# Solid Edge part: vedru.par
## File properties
Author: KULL
Template: Iso Metric Part.par
Last saved by: KULL
Revision: 3
Application: Solid Edge
Accuracy: 0,990
Face Style: Model Default
Fill Style: Normal
Coef. of Thermal Exp: 0.0
Thermal Conductivity: 0.0
Specific Heat: 0.0
Modulus of Elasticity: 0.0
Poisson's Ratio: 0.0
Yield Stress: 0.0
Ultimate Stress: 0.0
Elongation: 0.0
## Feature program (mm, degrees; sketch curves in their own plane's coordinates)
helix protrusion "HelixProtrusion_1"  NumberOfTurns = 4.5
sketch for "unnamed RevolvedProtrusion 1" plane through (0, 0, 0) normal (1, 0, 0) x-axis (0, 1, 0)
  circle centre (54.7904, 36.9537) radius 1.2
revolve "unnamed RevolvedProtrusion 1" add finite 360 deg
sketch for "unnamed RevolvedProtrusion 2" plane through (0, 0, 0) normal (1, 0, 0) x-axis (0, 1, 0)
  circle centre (78.3263, 18.3837) radius 1.2
revolve "unnamed RevolvedProtrusion 2" add finite 360 deg
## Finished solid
Body 1: solid body, 3 faces, 4 edges, 4 vertices.
  Faces by surface: torus 2, spline 1
  Edges by curve: circle 2, intersection 2
Bounding box of the edges (mm; curved faces can reach further): 6.787 x 25.640 x 26.544, from (-6.7872, 53.7383, 14.3974) to (0, 79.3784, 40.9412).
Toroidal faces (ring radius, tube radius in mm): R5.8516 r1.2 x2
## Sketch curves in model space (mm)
line (0, 73.196, 15.5693) -> (0, 59.9207, 39.7682)
circle centre (0, 54.7904, 36.9537) radius 1.2
circle centre (0, 78.3263, 18.3837) radius 1.2
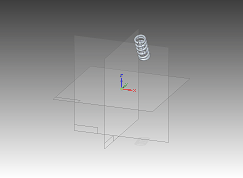
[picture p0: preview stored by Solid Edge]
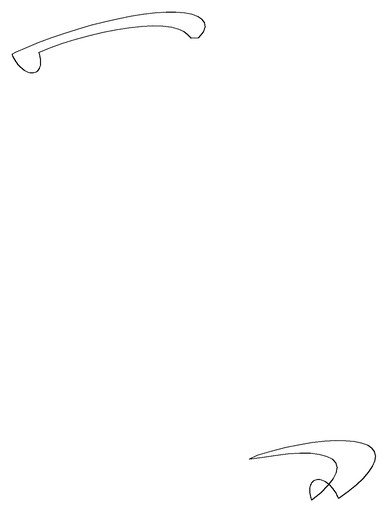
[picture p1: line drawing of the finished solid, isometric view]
